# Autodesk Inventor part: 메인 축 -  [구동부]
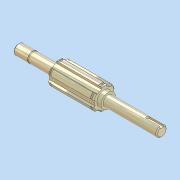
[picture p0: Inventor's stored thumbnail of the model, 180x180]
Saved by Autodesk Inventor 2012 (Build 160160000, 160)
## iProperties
Created: 2012-05
Part Number: 메인 축 -  [구동부]
Document SubType Name: 모델링
Designer: SeoGD™
Mass: 21.4462 g
Surface Area: 72.5109 cm^2
Volume: 21.4462 cm^3
Density: 1 g/cm^3
Material: 기본값
변환 표준: STEP AP214IS
파일 이름: C:\Users\SeoGD\Desktop\?쒗뿕\硫붿씤 異?.stp
전처리기: Build: 253, Release: 2010 SP1 - Date: Wed 07/29/2009
전송 단위: 밀리미터
불확실성: 0.01
Author: SeoGD™
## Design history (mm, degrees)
sketch "스케치1"
  geometry: L1 (-69.5, 0)-(69.5, 0); L2 (69.5, 0)-(69.5, 5); L3 (69.5, 5)-(55.5, 5); L4 (55.5, 5)-(55.5, 4.8); L5 (55.5, 4.8)-(54.35, 4.8); L6 (54.35, 4.8)-(54.35, 5); L7 (54.35, 5)-(30.5, 5); L8 (30.5, 5)-(30.5, 9); L9 (30.5, 9)-(-13.5, 9); L10 (-13.5, 9)-(-13.5, 7); L11 (-13.5, 7)-(-17.5, 7); L12 (-17.5, 7)-(-17.5, 5); L13 (-17.5, 5)-(-69.5, 5); L14 (-69.5, 5)-(-69.5, 0); 2 further points
  constraints: 28 end point, 9 parallel, 4 collinear, 2 perpendicular, 1 coincident, 1 horizontal, 1 midpoint
  dimensions: "d2" = 1.15 distance between parallel lines of L6 L4; "d3" = 10 diameter of L3 L1; "d4" = 9.6 diameter of L5 L1; "d6" = 44 distance between parallel lines of L10 L8; "d7" = 4 distance between parallel lines of L12 L10; "d8" = 14 diameter of L11 L1; "d9" = 18 diameter of L9 L1; "d33" = 52 distance from line of L12.end L14; "d37" = 39 distance between parallel lines of L8 L2; "d38" = 14 distance between parallel lines of L2 L4
revolve "회전1" sketch "스케치1" stored, may be unused: angle "d10" = 90 deg
sketch "스케치2"
  geometry: L1 (2.5, 10.712)-(2.5, 8.646); L2 (-2.5, 10.712)-(-2.5, 8.646); A1 r 9 centre (0, 0) between (2.5, 8.646) and (-2.5, 8.646) reference; A2 r 11 centre (0, 0) between (2.5, 10.712) and (-2.5, 10.712); 1 further point
  constraints: 4 end point, 4 point on circle, 2 parallel, 1 centre point, 1 coincident, 1 vertical
  dimensions: "d11" = 22 diameter of A2; "d12" = 5 distance between parallel lines of L1 L2
extrude "돌출1" join sketch "스케치2" stored distance "d13" = 10; taper "d14" = 0 deg
chamfer "모따기1" distance "d15" = 1; stored, may be unused: second distance "d16" = 2, angle "d17" = 45 deg
node "작업 평면1"
node "작업 평면2"
sketch "스케치3"
  geometry: L1 (2.5, 10.712)-(2.5, 10.198); L2 (-2.5, 10.712)-(-2.5, 10.198); A1 r 11 centre (0, 0) between (2.5, 10.712) and (-2.5, 10.712) reference; A2 r 10.5 centre (0, 0) between (2.5, 10.198) and (-2.5, 10.198); 1 further point
  constraints: 4 end point, 2 point on circle, 1 centre point, 1 coincident, 1 parallel, 1 vertical
  dimensions: "d19" = 21 diameter of A2
extrude "돌출2" cut sketch "스케치3" distance "d20" = 1.35; taper "d21" = 0 deg
node "작업 평면3"
sketch "스케치4"
  geometry: L1 (-26, -5)-(-26, 5) reference; L2 (-26, 1.5)-(-12.5, 1.5); L3 (-12.5, -1.5)-(-26, -1.5); A1 r 1.5 centre (-12.5, 0) between (-12.5, -1.5) and (-12.5, 1.5); 2 further points
  constraints: 4 end point, 2 perpendicular, 2 point on circle, 2 point on line, 2 tangent, 1 centre point, 1 horizontal alignment, 1 midpoint
  dimensions: "d25" = 3 distance between parallel lines of L3 L2; "d26" = 15 dimension on A1 L1
extrude "돌출3" cut sketch "스케치4" distance "d27" = 1.8; taper "d28" = 0 deg
chamfer "모따기2" distance "d29" = 1; stored, may be unused: second distance "d30" = 2, angle "d31" = 45 deg
node "솔리드1"
node "솔리드 본체"
node "곡면 본체"
mirror "대칭1"
pattern_circular "원형 패턴1" dims "d23" = 360 deg
node "솔리드2"
other parameters: "d18" = -1.65
